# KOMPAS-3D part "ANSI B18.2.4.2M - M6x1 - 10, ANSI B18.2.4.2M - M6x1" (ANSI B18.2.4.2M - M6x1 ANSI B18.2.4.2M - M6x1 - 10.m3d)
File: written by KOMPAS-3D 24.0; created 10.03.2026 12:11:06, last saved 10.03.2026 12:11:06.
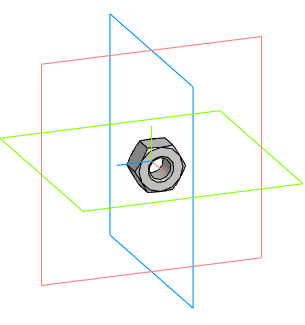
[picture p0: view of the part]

Document properties: Автор: R2D2; Полное имя файла: E:\Работа\Зайцев\BV3232P(4pc)-FP-3WL-F-ISO-H Кран шаровой DN.ru Ду15-100 Ру16\DN25\исходные материалы\ANSI B18.2.4.2M - M6x1 ANSI B18.2.4.2M - M6x1 - 10.m3d

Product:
- Body: Solid1  | qty 1
- Part/product: ANSI B18.2.4.2M - M6x1 - 10  | designation ANSI B18.2.4.2M - M6x1
    Комментарий: Типы метрических   шестигранных гаек   2
    additional columns: Сталь, мягкая

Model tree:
1. Solid1  (labels: Solid1)

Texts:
  ANSI B18.2.4.2M - M6x1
